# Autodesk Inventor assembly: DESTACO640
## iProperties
Title: DESTACO640
Author: GJOHNST2
Shininess: 20.0
Length Units: 11272
Angle Units: 11286
Time Units: 11279
Mass Units: 11290
Length Display Precision: 3
Angle Display Precision: 0
Compacted: True
PropertySet Name: _Private Model Information
Created: 2001-11
Part Number: DESTACO640
Document SubType Name: Assembly
Designer: GJOHNST2
Control State: 0
Master: False
Checked Out: False
PropertySet Name: Design Tracking Control
Density: 0.0
Volumn: 0.0
Area: 0.0
PropertySet Name: Model Information
